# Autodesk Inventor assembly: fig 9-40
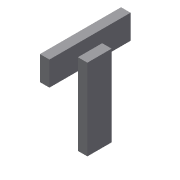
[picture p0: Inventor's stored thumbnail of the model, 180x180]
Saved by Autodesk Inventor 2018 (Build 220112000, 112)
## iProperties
Created: 2013-07
Part Number: fig 9-40
Document SubType Name: Assembly
Designer: CADCIM
Author: CADCIM
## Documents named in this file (2)
- E:\_Deepak\Inventor\Autodesk Inventor_2017_Project\Resources\Inventor_2018_Part\c09_Inv_2018\c09_inv_2018_prt\fig 9-40.iam
- E:\_Deepak\Inventor\Autodesk Inventor_2017_Project\Resources\Inventor_2018_Part\c09_Inv_2018\c09_inv_2018_prt\12.ipt
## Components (2 placed, 1 different names)
1. 12:1 — Rigid:1
2. 12:2 — Rigid:1
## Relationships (1: WeldJoint 1)
- Rigid:1 [WeldJoint]: 12:1 ↔ 12:2
